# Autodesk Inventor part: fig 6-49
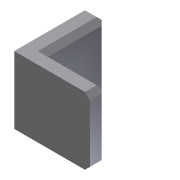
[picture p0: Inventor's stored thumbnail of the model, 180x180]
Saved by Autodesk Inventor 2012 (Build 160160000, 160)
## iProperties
Created: 2009-09
Part Number: fig 6-49
Document SubType Name: Modeling
Designer: Sham
Density: 1 g/cm^3
Material: Default
Author: Sham
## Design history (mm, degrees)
sketch "Sketch1"
  geometry: L1 (1.789, 30)-(1.789, -5); L2 (1.789, -5)-(36.789, -5); L3 (36.789, -5)-(36.789, -15); L4 (36.789, -15)-(-8.211, -15); L5 (-8.211, -15)-(-8.211, 30); L6 (-8.211, 30)-(1.789, 30)
  constraints: 12 end point, 6 perpendicular
  dimensions: "d0" = 10 distance of L5.end L1.start; "d1" = 35 distance of L1.start L1.end; "d2" = 45 distance of L3.end L4.end; "d3" = 10 distance of L2.end L3.end (derived)
extrude "Extrusion1" new body sketch "Sketch1" distance "d4" = 40; taper "d5" = 0 deg
chamfer "Chamfer1" distance "d6" = 3; stored, may be unused: second distance "d7" = 2, angle "d8" = 45 deg
body "Solid1"
other parameters: "d1" = 35
